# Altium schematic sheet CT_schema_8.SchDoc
size 274 x 160 mm
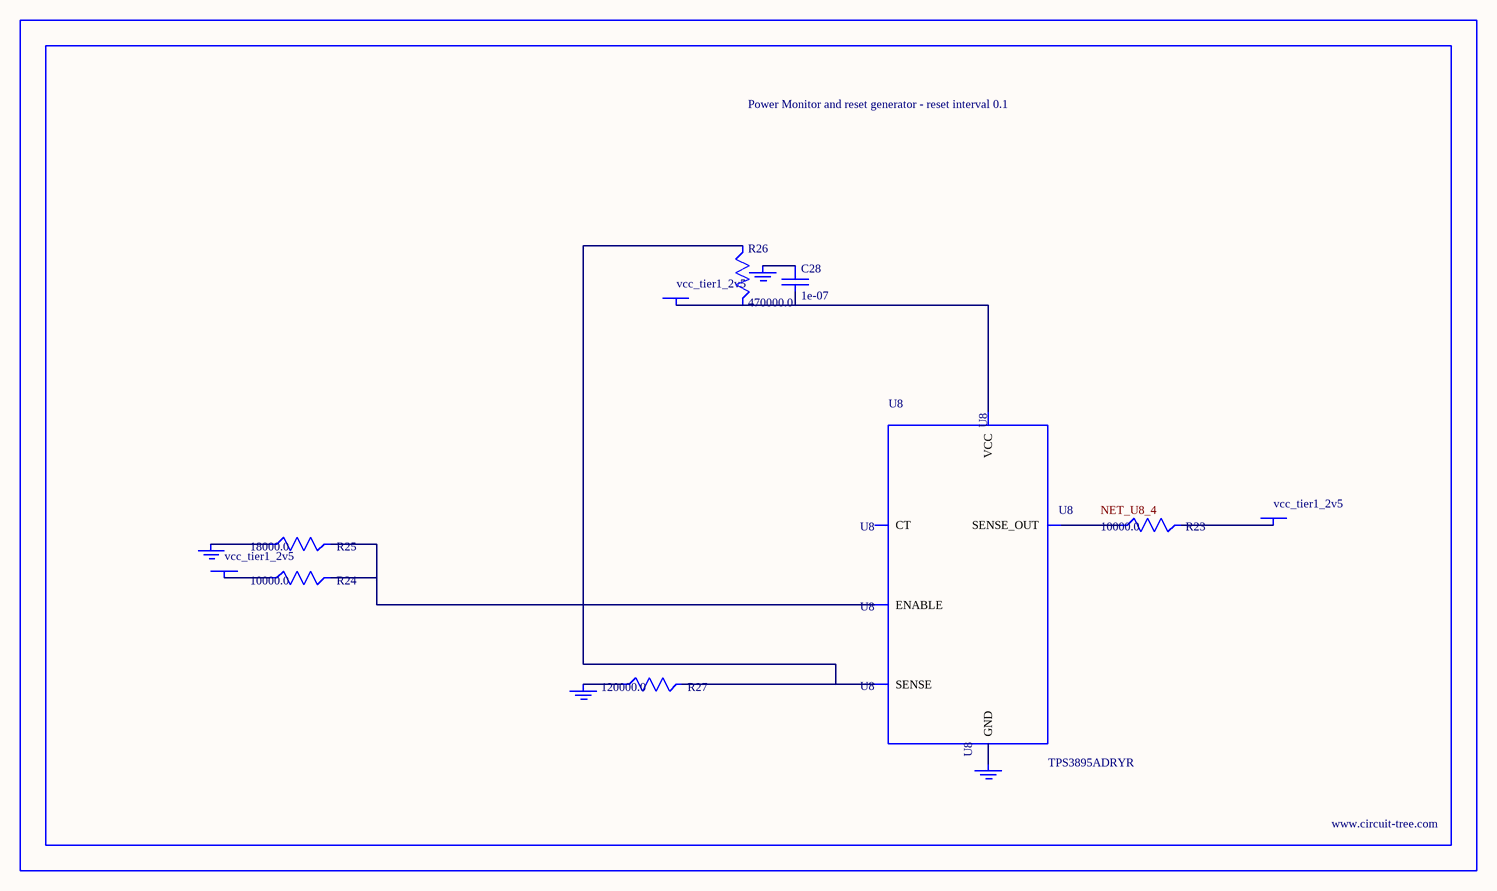
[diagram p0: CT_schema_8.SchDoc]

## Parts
BORDER7  (no value)
C28  1e-07  [C0402]
GND_INSTANCE_7_0  (no value)
GND_INSTANCE_7_1  (no value)
GND_INSTANCE_7_2  (no value)
GND_INSTANCE_7_3  (no value)
POWER_INSTANCE_7_0  vcc_tier1_2v5
POWER_INSTANCE_7_1  vcc_tier1_2v5
POWER_INSTANCE_7_2  vcc_tier1_2v5
R23  10000.0  [R0603]
R24  10000.0  [R0603]
R25  18000.0  [R0603]
R26  470000.0  [R0603]
R27  120000.0  [R0603]
U8  TPS3895ADRYR  [SON-6]

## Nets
NetC28_1: C28.1 GND_INSTANCE_7_2.0(GND)
NetC28_2: C28.2 POWER_INSTANCE_7_2.0(PWR) R26.2 U8.6(VCC)
NetGND_INSTANCE_7_0_0: GND_INSTANCE_7_0.0(GND) R25.1
NetGND_INSTANCE_7_1_0: GND_INSTANCE_7_1.0(GND) R27.1
NetGND_INSTANCE_7_3_0: GND_INSTANCE_7_3.0(GND) U8.2(GND)
NetPOWER_INSTANCE_7_0_0: POWER_INSTANCE_7_0.0(PWR) R24.1
NetPOWER_INSTANCE_7_1_0: POWER_INSTANCE_7_1.0(PWR) R23.2
NetR23_1: R23.1 U8.4(SENSE_OUT)
NetR24_2: R24.2 R25.2 U8.1(ENABLE)
NetR26_1: R26.1 R27.2 U8.3(SENSE)

Not connected (* = marked no-connect by the designer): U8 5(CT)

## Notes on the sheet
- Labels drawn without touching a wire or pin: NET_U8_4

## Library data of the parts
BORDER7 = BORDER_PAGE7
C28 = C0402C104K3RACTU
GND_INSTANCE_7_0-GND_INSTANCE_7_3 = GND
POWER_INSTANCE_7_0-POWER_INSTANCE_7_2 = PWR
R23 R24 = RC0603JR-0710KL
R25 = RC0603JR-0718KL
R26 = RC0603JR-07470KL
R27 = RC0603JR-07120KL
